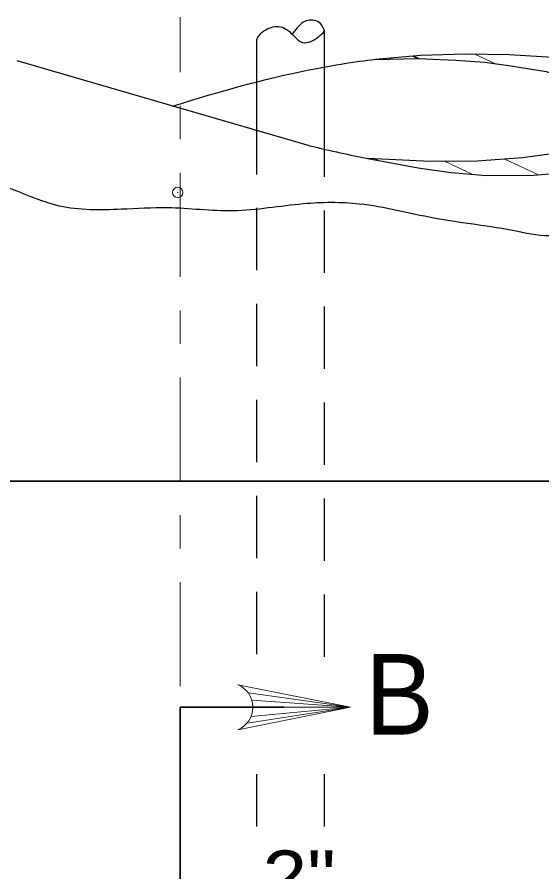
# Model space of a CAD drawing. Extents: x 1083.1 to 1117.1, y 719.4 to 741.4.
# Drawn here: x 1101.585 to 1103.15, y 729.047 to 731.595 of the extents above; entities that cross this region are included whole.
import ezdxf
from ezdxf.enums import TextEntityAlignment as Align

# ---------------------------------------------------------------- set-up
doc = ezdxf.new("R2010")
doc.units = 0
doc.header["$LTSCALE"] = 0.062
doc.header["$PDMODE"] = 32
doc.header["$PDSIZE"] = 0.031
doc.linetypes.add('DOT_DASHED', pattern=[7.7, 5, -1.2, 0.3, -1.2])
doc.linetypes.add('MEDIUM_DASHED', pattern=[4.5, 3, -1.5])
doc.layers.add('1', color=7, linetype='Continuous', lineweight=13)

msp = doc.modelspace()

# ---------------------------------------------------------------- linework, layer by layer
at = {"layer": '1', "linetype": 'DOT_DASHED'}
msp.add_line((1102.07067, 729.6005), (1102.07067, 731.59458), dxfattribs=at)
at = {"layer": '1', "lineweight": 25}
for p, q in [((1102.50175, 731.20458), (1102.50175, 731.55258)), ((1102.29925, 731.26083), (1102.29925, 731.52742)), ((1102.45642, 731.21133), (1101.585, 731.46383)), ((1103.25025, 730.21208), (1100.8715, 730.21208))]:
    msp.add_line(p, q, dxfattribs=at)
at = {"layer": '1'}
for p, q in [((1102.77783, 731.47142), (1102.76358, 731.47808)), ((1102.78367, 731.47133), (1102.76858, 731.47842)), ((1103.00917, 731.45608), (1102.94967, 731.48392)), ((1102.70183, 731.46942), (1102.69633, 731.472)), ((1102.63817, 731.17142), (1102.63575, 731.17267)), ((1102.66242, 731.167), (1102.652, 731.17183)), ((1102.94175, 731.12658), (1102.86083, 731.1645)), ((1103.13925, 731.12458), (1103.03875, 731.1715)), ((1102.27442, 729.5805), (1102.57892, 729.53792)), ((1102.28475, 729.55942), (1102.57892, 729.53792)), ((1102.27083, 729.49083), (1102.57892, 729.53792)), ((1102.2825, 729.51058), (1102.57892, 729.53792)), ((1102.28792, 729.53792), (1102.57892, 729.53792))]:
    msp.add_line(p, q, dxfattribs=at)
at = {"layer": '1', "linetype": 'MEDIUM_DASHED', "lineweight": 25}
for p, q in [((1102.29925, 729.696), (1102.29925, 731.26083)), ((1102.50175, 729.68808), (1102.50175, 731.20458)), ((1102.29925, 729.18242), (1102.29925, 729.33875)), ((1102.50175, 729.18242), (1102.50175, 729.33875))]:
    msp.add_line(p, q, dxfattribs=at)
at = {"layer": '1', "lineweight": 35}
for p, q in [((1102.07067, 729.53792), (1102.38108, 729.53792)), ((1102.07067, 728.78608), (1102.07067, 729.53792))]:
    msp.add_line(p, q, dxfattribs=at)
at = {"layer": '1', "lineweight": 25}
for points in [[(1102.63025, 731.17292), (1102.78067, 731.14542), (1102.87883, 731.13175), (1102.98408, 731.123), (1103.12483, 731.12342), (1103.23217, 731.13225), (1103.37175, 731.16417), (1103.45858, 731.20775), (1103.51333, 731.25633), (1103.53133, 731.296), (1103.50942, 731.35283), (1103.46292, 731.39183), (1103.3995, 731.428), (1103.31042, 731.45533), (1103.19808, 731.47358), (1103.05233, 731.48258), (1102.92167, 731.48433), (1102.788, 731.48017), (1102.65317, 731.46808)], [(1102.65317, 731.46808), (1102.78008, 731.4715), (1102.89283, 731.46633), (1102.97908, 731.46008), (1103.05658, 731.44975), (1103.16275, 731.43217), (1103.22692, 731.41258), (1103.28217, 731.39183), (1103.32625, 731.36692), (1103.34842, 731.32967), (1103.3375, 731.26767), (1103.28658, 731.22308), (1103.187, 731.188), (1103.092, 731.1755), (1102.95708, 731.16525), (1102.81767, 731.16417), (1102.63025, 731.17292)], [(1100.59642, 730.21208), (1100.8715, 730.21208), (1103.25025, 730.21208)]]:
    msp.add_lwpolyline(points, dxfattribs=at)
at = {"layer": '1'}
msp.add_lwpolyline([(1102.24258, 729.47067), (1102.57892, 729.53792), (1102.24258, 729.60517)], dxfattribs=at)
msp.add_arc((1102.21545, 729.538), 0.07258, 292.08605, 67.91218, dxfattribs=at)
at = {"layer": '1', "lineweight": 25}
for points in [[(1102.50175, 731.55258), (1102.48908, 731.57533), (1102.4515, 731.58475), (1102.42017, 731.56283), (1102.40425, 731.5425)], [(1102.29925, 731.52742), (1102.30742, 731.54092), (1102.32617, 731.5565), (1102.37008, 731.56592), (1102.41083, 731.53775), (1102.43583, 731.519), (1102.46092, 731.52208), (1102.50175, 731.55258)], [(1100.87175, 731.16117), (1100.94592, 731.127), (1101.08283, 731.10458), (1101.28125, 731.09775), (1101.44358, 731.11633), (1101.5415, 731.09292), (1101.71075, 731.03258), (1101.896, 731.02283), (1102.03275, 731.02708), (1102.22933, 731.01817), (1102.43817, 731.03883), (1102.60525, 731.03842), (1102.82767, 730.99642), (1103.07767, 730.9565), (1103.184, 730.94542), (1103.25025, 730.96675)]]:
    msp.add_spline(points, degree=3, dxfattribs=at)
for points in [[(1102.65317, 731.46808), (1102.53583, 731.45383), (1102.34775, 731.42408), (1102.04583, 731.32767)], [(1102.45642, 731.21133), (1102.5205, 731.19617), (1102.57833, 731.18358), (1102.63025, 731.17292)]]:
    msp.add_open_spline(points, degree=3, dxfattribs=at)
at = {"layer": '1'}
msp.add_point((1102.06383, 731.072), dxfattribs=at)

# ---------------------------------------------------------------- texts
for s, height, width, p in [('B', 0.24, 0.95, (1102.72517, 729.4565)), ('2"', 0.156, 1.15, (1102.42579, 728.955))]:
    msp.add_text(s, height=height, dxfattribs=dict(at, width=width)).set_placement(p, align=Align.CENTER)

doc.saveas('drawing.dxf')
